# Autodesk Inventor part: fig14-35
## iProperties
Created: 2005-03
Part Number: fig14-35
Document SubType Name: Sheet Metal
Designer: CADCIM
Manufacturer: Standard
Standards Organization: Custom
Author: CADCIM
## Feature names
1. Plate1
2. Plate2
3. Bend1
4. Plate3
5. Bend2
